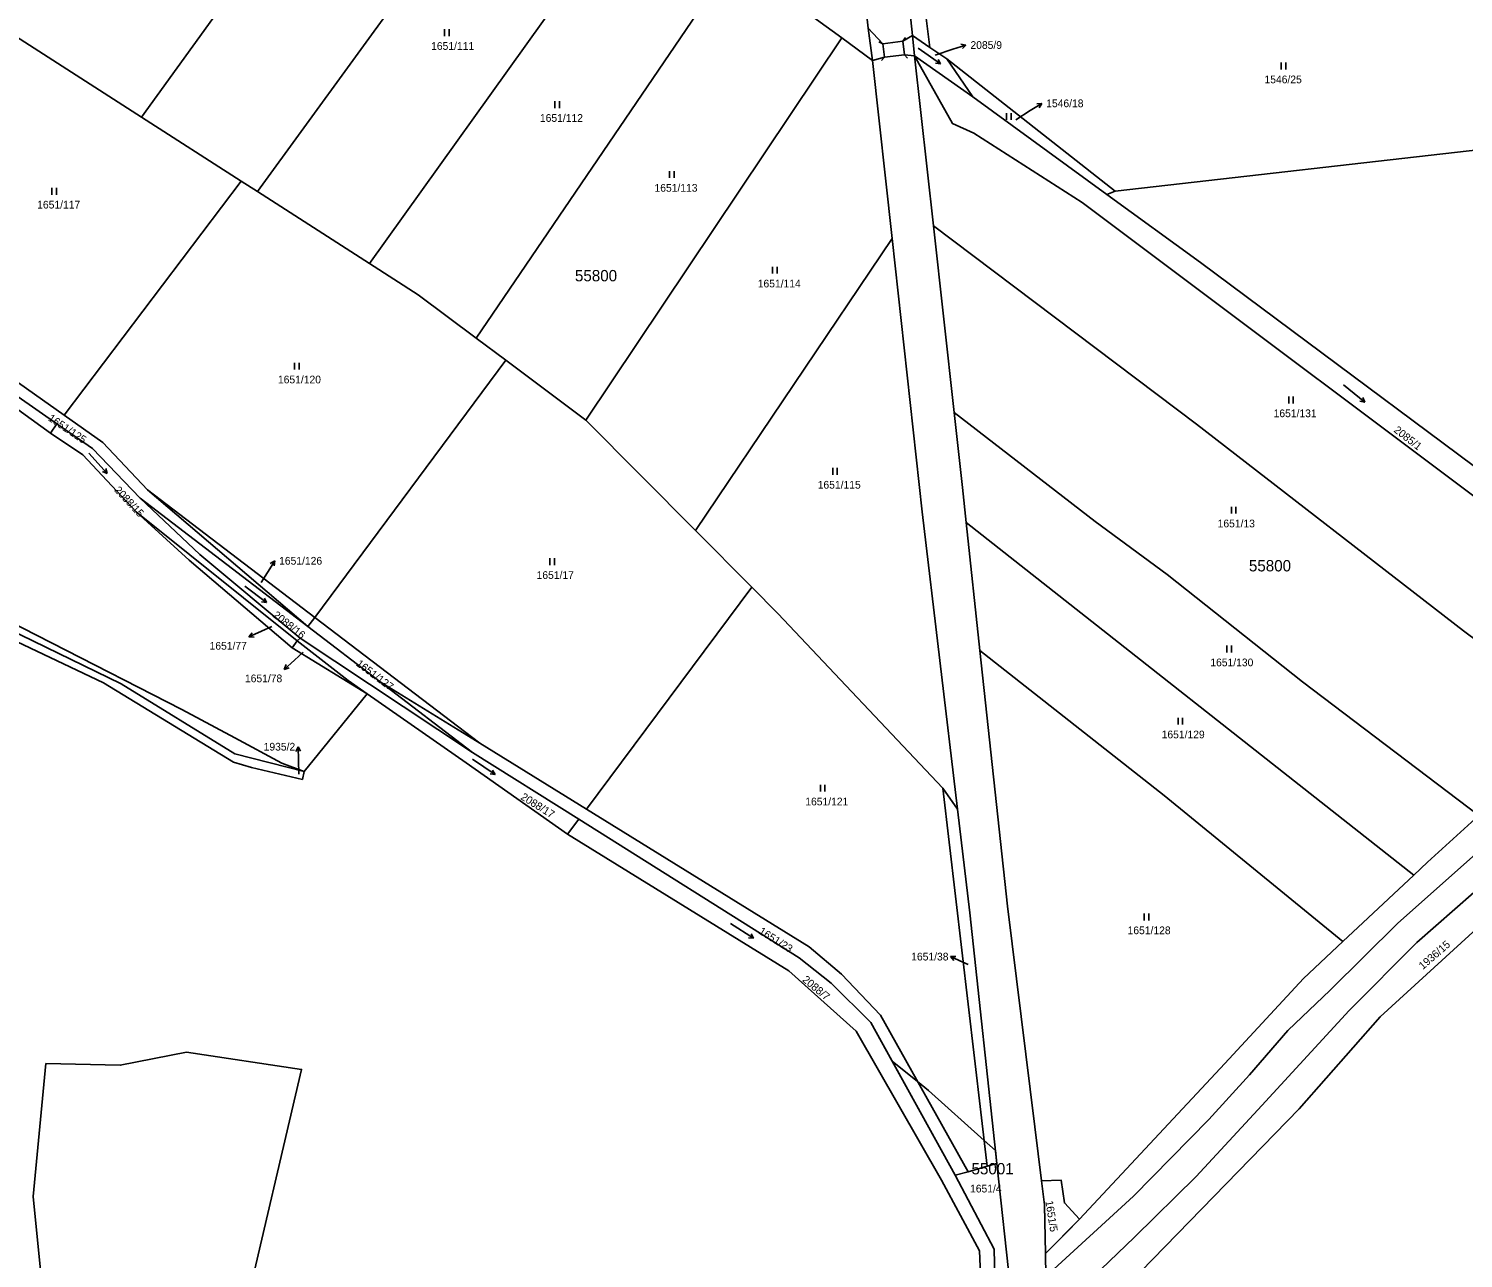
# Model space of a CAD drawing. Extents: x -794765 to -785424, y -1118958 to -1108731.
# Drawn here: x -792685.9 to -792369.7, y -1111701.3 to -1111430.3 of the extents above; entities that cross this region are included whole.
import ezdxf

# ---------------------------------------------------------------- set-up
doc = ezdxf.new("R2010")
doc.units = 0
for name, color, linetype in [('Level 66', 7, 'Continuous'), ('Level 75', 7, 'Continuous'), ('Level 76', 7, 'Continuous'), ('Level 77', 7, 'Continuous'), ('Level 80', 7, 'Continuous'), ('Level 81', 7, 'Continuous'), ('Vrstva 53', 7, 'Continuous')]:
    doc.layers.add(name, color=color, linetype=linetype)

msp = doc.modelspace()

# ---------------------------------------------------------------- linework, layer by layer
at = {"layer": 'Level 66'}
for p, q in [((-792594.27, -1111431.92), (-792594.27, -1111430.42)), ((-792593.27, -1111431.92), (-792593.27, -1111430.42)), ((-792489.85, -1111434.6), (-792484.93, -1111438.04)), ((-792484.93, -1111438.04), (-792486.02, -1111437.89)), ((-792484.93, -1111438.04), (-792485.45, -1111437.07)), ((-792409.84, -1111439.29), (-792409.84, -1111437.79)), ((-792408.84, -1111439.29), (-792408.84, -1111437.79)), ((-792569.92, -1111447.79), (-792569.92, -1111446.29)), ((-792568.92, -1111447.79), (-792568.92, -1111446.29)), ((-792470.35, -1111450.39), (-792470.35, -1111448.89)), ((-792469.35, -1111450.39), (-792469.35, -1111448.89)), ((-792544.65, -1111463.19), (-792544.65, -1111461.69)), ((-792543.65, -1111463.19), (-792543.65, -1111461.69)), ((-792680.84, -1111466.89), (-792680.84, -1111465.39)), ((-792679.84, -1111466.89), (-792679.84, -1111465.39)), ((-792521.97, -1111484.28), (-792521.97, -1111482.78)), ((-792520.97, -1111484.28), (-792520.97, -1111482.78)), ((-792627.34, -1111505.43), (-792627.34, -1111503.93)), ((-792626.34, -1111505.43), (-792626.34, -1111503.93)), ((-792396.07, -1111508.83), (-792391.41, -1111512.6)), ((-792408.17, -1111512.88), (-792408.17, -1111511.38)), ((-792407.17, -1111512.88), (-792407.17, -1111511.38)), ((-792391.41, -1111512.6), (-792392.49, -1111512.38)), ((-792391.41, -1111512.6), (-792391.85, -1111511.6)), ((-792672.67, -1111523.86), (-792668.66, -1111528.32)), ((-792668.66, -1111528.32), (-792669.68, -1111527.93)), ((-792668.66, -1111528.32), (-792668.94, -1111527.26)), ((-792508.7, -1111528.63), (-792508.7, -1111527.13)), ((-792507.7, -1111528.63), (-792507.7, -1111527.13)), ((-792420.81, -1111537.16), (-792420.81, -1111535.66)), ((-792419.81, -1111537.16), (-792419.81, -1111535.66)), ((-792571.05, -1111548.53), (-792571.05, -1111547.03)), ((-792570.05, -1111548.53), (-792570.05, -1111547.03)), ((-792638.3, -1111553.18), (-792633.51, -1111556.79)), ((-792633.51, -1111556.79), (-792634.59, -1111556.6)), ((-792633.51, -1111556.79), (-792633.98, -1111555.8)), ((-792421.79, -1111567.78), (-792421.79, -1111566.28)), ((-792420.79, -1111567.78), (-792420.79, -1111566.28)), ((-792432.55, -1111583.66), (-792432.55, -1111582.16)), ((-792431.55, -1111583.66), (-792431.55, -1111582.16)), ((-792588.11, -1111591.34), (-792583.13, -1111594.69)), ((-792583.13, -1111594.69), (-792584.22, -1111594.56)), ((-792583.13, -1111594.69), (-792583.66, -1111593.73)), ((-792511.42, -1111598.44), (-792511.42, -1111596.94)), ((-792510.42, -1111598.44), (-792510.42, -1111596.94)), ((-792531.19, -1111627.49), (-792526.15, -1111630.76)), ((-792440.04, -1111626.83), (-792440.04, -1111625.33)), ((-792439.04, -1111626.83), (-792439.04, -1111625.33)), ((-792526.15, -1111630.76), (-792527.25, -1111630.65)), ((-792526.15, -1111630.76), (-792526.7, -1111629.81))]:
    msp.add_line(p, q, dxfattribs=at)
at = {"layer": 'Level 75'}
for p, q in [((-792661.06, -1111449.81), (-792600.1, -1111365.36)), ((-792635.5, -1111466.22), (-792575.06, -1111383.02)), ((-792610.83, -1111482.05), (-792551.75, -1111399.53)), ((-792587.28, -1111498.52), (-792530.56, -1111414.97)), ((-792530.56, -1111414.97), (-792506.69, -1111432.36)), ((-792487.27, -1111434.43), (-792488.15, -1111427.37)), ((-792693.59, -1111428.94), (-792661.06, -1111449.81)), ((-792499.9, -1111437.31), (-792500.86, -1111430.2)), ((-792563.09, -1111516.61), (-792506.69, -1111432.36)), ((-792506.69, -1111432.36), (-792499.9, -1111437.31)), ((-792487.27, -1111434.43), (-792491.13, -1111431.81)), ((-792491.13, -1111431.81), (-792490.63, -1111436.28)), ((-792483.54, -1111436.96), (-792487.27, -1111434.43)), ((-792499.9, -1111437.31), (-792495.59, -1111476.54)), ((-792490.63, -1111436.28), (-792477.82, -1111445.31)), ((-792486.49, -1111473.79), (-792490.63, -1111436.28)), ((-792477.82, -1111445.31), (-792483.54, -1111436.96)), ((-792446.42, -1111466.11), (-792483.54, -1111436.96)), ((-792448.26, -1111466.82), (-792477.82, -1111445.31)), ((-792661.06, -1111449.81), (-792639.08, -1111463.92)), ((-792446.42, -1111466.11), (-792336.43, -1111453.6)), ((-792678.13, -1111515.48), (-792639.08, -1111463.92)), ((-792639.08, -1111463.92), (-792635.5, -1111466.22)), ((-792635.5, -1111466.22), (-792610.83, -1111482.05)), ((-792448.26, -1111466.82), (-792446.42, -1111466.11)), ((-792486.49, -1111473.79), (-792481.94, -1111514.93)), ((-792538.93, -1111540.93), (-792495.59, -1111476.54)), ((-792711.08, -1111495.6), (-792679.73, -1111517.41)), ((-792701.37, -1111499.06), (-792678.13, -1111515.48)), ((-792587.28, -1111498.52), (-792580.77, -1111503.39)), ((-792580.77, -1111503.39), (-792622.84, -1111560.08)), ((-792563.09, -1111516.61), (-792580.77, -1111503.39)), ((-792538.93, -1111540.93), (-792563.09, -1111516.61)), ((-792681.1, -1111519.43), (-792679.73, -1111517.41)), ((-792659.73, -1111531.96), (-792622.84, -1111560.08)), ((-792624.37, -1111562.09), (-792659.73, -1111531.96)), ((-792661.39, -1111533.79), (-792624.37, -1111562.09)), ((-792626.76, -1111565.23), (-792662.23, -1111536.79)), ((-792476.24, -1111567.39), (-792479.28, -1111539.17)), ((-792380.6, -1111616.86), (-792479.28, -1111539.17)), ((-792526.51, -1111553.43), (-792538.93, -1111540.93)), ((-792562.99, -1111602.32), (-792526.51, -1111553.43)), ((-792710.23, -1111555.16), (-792669.41, -1111574.48)), ((-792624.37, -1111562.09), (-792622.84, -1111560.08)), ((-792622.84, -1111560.08), (-792586.5, -1111587.78)), ((-792624.37, -1111562.09), (-792608.44, -1111574.27)), ((-792627.85, -1111566.78), (-792626.76, -1111565.23)), ((-792611.35, -1111576.91), (-792627.85, -1111566.78)), ((-792626.76, -1111565.23), (-792626.11, -1111564.6)), ((-792626.11, -1111564.6), (-792588.08, -1111589.84)), ((-792669.41, -1111574.48), (-792640.78, -1111591.95)), ((-792625.2, -1111594.04), (-792611.35, -1111576.91)), ((-792586.5, -1111587.78), (-792608.44, -1111574.27)), ((-792608.44, -1111574.27), (-792588.08, -1111589.84)), ((-792588.08, -1111589.84), (-792564.67, -1111604.56)), ((-792586.5, -1111587.78), (-792562.99, -1111602.32)), ((-792640.78, -1111591.95), (-792636.82, -1111593.12)), ((-792484.4, -1111597.73), (-792474.62, -1111681.02)), ((-792481.17, -1111602.31), (-792484.4, -1111597.73)), ((-792564.67, -1111604.56), (-792567.14, -1111607.86)), ((-792380.6, -1111616.86), (-792396.21, -1111631.51)), ((-792474.62, -1111681.02), (-792478.83, -1111682.26)), ((-792472.48, -1111680.42), (-792474.62, -1111681.02)), ((-792472.48, -1111680.42), (-792469.49, -1111708.06)), ((-792478.83, -1111682.26), (-792481.68, -1111682.99)), ((-792454.29, -1111692.72), (-792461.78, -1111700.29))]:
    msp.add_line(p, q, dxfattribs=at)
for points in [[(-792491.13, -1111431.81), (-792491.51, -1111428.33), (-792497.74, -1111372.23)], [(-792490.63, -1111436.28), (-792482.27, -1111451.23), (-792477.59, -1111453.34), (-792453.68, -1111468.58), (-792349.47, -1111546.81)], [(-792339.24, -1111548.69), (-792343.91, -1111544.15), (-792427.64, -1111481.83), (-792448.26, -1111466.82)], [(-792343.17, -1111582.69), (-792369.63, -1111563.05), (-792428.51, -1111517.47), (-792486.49, -1111473.79)], [(-792495.59, -1111476.54), (-792488.97, -1111536.76), (-792481.17, -1111602.31)], [(-792610.83, -1111482.05), (-792600.05, -1111488.97), (-792587.28, -1111498.52)], [(-792681.1, -1111519.43), (-792711.34, -1111497.65), (-792713.25, -1111495.39)], [(-792678.13, -1111515.48), (-792669.61, -1111521.5), (-792659.73, -1111531.96)], [(-792479.28, -1111539.17), (-792480.12, -1111531.4), (-792481.94, -1111514.93)], [(-792481.94, -1111514.93), (-792450.85, -1111538.95), (-792434.95, -1111550.6), (-792405.11, -1111574.24), (-792366.26, -1111603.72)], [(-792662.23, -1111536.79), (-792674.02, -1111524.21), (-792681.1, -1111519.43)], [(-792679.73, -1111517.41), (-792671.89, -1111522.86), (-792661.39, -1111533.79)], [(-792626.11, -1111564.6), (-792648.22, -1111546.21), (-792661.39, -1111533.79)], [(-792627.85, -1111566.78), (-792650.58, -1111547.47), (-792662.23, -1111536.79)], [(-792709.69, -1111550.99), (-792652.17, -1111580.36), (-792640.47, -1111586.61), (-792630.1, -1111592.15), (-792625.2, -1111594.04)], [(-792709.89, -1111553.21), (-792665.52, -1111574.73), (-792640.49, -1111590.16), (-792625.2, -1111594.04)], [(-792526.51, -1111553.43), (-792520.8, -1111559.18), (-792484.4, -1111597.73)], [(-792611.35, -1111576.91), (-792615.54, -1111574), (-792626.76, -1111565.23)], [(-792462.65, -1111684.23), (-792464.15, -1111672.32), (-792470.18, -1111623.67), (-792476.24, -1111567.39)], [(-792396.21, -1111631.51), (-792435.63, -1111599.33), (-792476.24, -1111567.39)], [(-792611.35, -1111576.91), (-792589.53, -1111592.09), (-792567.14, -1111607.86)], [(-792461.51, -1111714.48), (-792449.61, -1111703.78), (-792442.2, -1111696.63), (-792428.56, -1111683.25), (-792414.13, -1111667.62), (-792394.83, -1111646.68), (-792379.95, -1111631.73), (-792358.99, -1111613.36), (-792335.63, -1111592.95), (-792316, -1111574.96), (-792315.09, -1111574.03)], [(-792461.41, -1111719.58), (-792443.5, -1111707.04), (-792405.88, -1111668.37), (-792387.98, -1111648.11), (-792359.94, -1111622.42), (-792311.35, -1111577.41)], [(-792636.82, -1111593.12), (-792625.6, -1111595.75), (-792625.2, -1111594.04)], [(-792478.83, -1111682.26), (-792498.18, -1111647.73), (-792506.75, -1111638.68), (-792513.86, -1111632.7), (-792562.99, -1111602.32)], [(-792472.48, -1111680.42), (-792478.45, -1111625.15), (-792481.17, -1111602.31)], [(-792564.67, -1111604.56), (-792516.09, -1111635.11), (-792509.06, -1111640.65), (-792500.3, -1111649.32), (-792481.68, -1111682.99)], [(-792366.26, -1111603.72), (-792377.58, -1111614.03), (-792380.6, -1111616.86)], [(-792567.14, -1111607.86), (-792518.38, -1111637.95), (-792503.52, -1111651.22), (-792484.69, -1111684.09), (-792476.33, -1111699.64), (-792475.74, -1111713.71)], [(-792396.21, -1111631.51), (-792404.9, -1111639.66), (-792422.23, -1111658.36), (-792454.29, -1111692.72)], [(-792651.15, -1111655.88), (-792665.74, -1111658.77), (-792682.13, -1111658.41), (-792684.95, -1111687.66), (-792682.27, -1111714.24), (-792680.86, -1111742.68), (-792684.79, -1111773.8)], [(-792638.49, -1111714.03), (-792625.78, -1111659.69), (-792651.15, -1111655.88)], [(-792481.68, -1111682.99), (-792473.08, -1111699.31), (-792472.84, -1111711.97)], [(-792462.65, -1111684.23), (-792458.31, -1111684.1), (-792457.6, -1111689.12), (-792454.29, -1111692.72)], [(-792461.78, -1111700.29), (-792461.99, -1111689.5), (-792462.65, -1111684.23)], [(-792461.78, -1111700.29), (-792461.68, -1111705.3), (-792461.51, -1111714.48)]]:
    msp.add_lwpolyline(points, dxfattribs=at)
at = {"layer": 'Level 77'}
for p, q in [((-792500.86, -1111430.2), (-792497.65, -1111433.63)), ((-792498.55, -1111433.19), (-792497.65, -1111433.63)), ((-792497.65, -1111433.63), (-792493.26, -1111433.03)), ((-792497.65, -1111433.63), (-792497.3, -1111436.57)), ((-792493.26, -1111433.03), (-792491.13, -1111431.81)), ((-792492.62, -1111432.26), (-792493.26, -1111433.03)), ((-792493.26, -1111433.03), (-792492.9, -1111436.04)), ((-792499.9, -1111437.31), (-792497.3, -1111436.57)), ((-792497.93, -1111437.35), (-792497.3, -1111436.57)), ((-792497.3, -1111436.57), (-792492.9, -1111436.04)), ((-792492.23, -1111436.78), (-792492.9, -1111436.04)), ((-792492.9, -1111436.04), (-792490.63, -1111436.28)), ((-792384.11, -1111627.47), (-792363.02, -1111608.73)), ((-792399.06, -1111642.23), (-792384.11, -1111627.47)), ((-792399.06, -1111642.23), (-792408.36, -1111651.07)), ((-792408.36, -1111651.07), (-792416.83, -1111660.88)), ((-792416.83, -1111660.88), (-792425.75, -1111670.7)), ((-792425.75, -1111670.7), (-792442.4, -1111687.65)), ((-792442.4, -1111687.65), (-792461.68, -1111705.3))]:
    msp.add_line(p, q, dxfattribs=at)
at = {"layer": 'Level 80'}
for p, q in [((-792486.08, -1111436.12), (-792482.18, -1111434.84)), ((-792482.18, -1111434.84), (-792479.33, -1111433.91)), ((-792479.33, -1111433.91), (-792480.43, -1111433.75)), ((-792479.33, -1111433.91), (-792480.12, -1111434.7)), ((-792465.16, -1111448.37), (-792462.61, -1111446.78)), ((-792462.61, -1111446.78), (-792463.73, -1111446.89)), ((-792462.61, -1111446.78), (-792463.2, -1111447.74)), ((-792468.34, -1111450.39), (-792465.16, -1111448.37)), ((-792633.3, -1111550.14), (-792631.71, -1111547.59)), ((-792631.71, -1111547.59), (-792632.67, -1111548.18)), ((-792631.71, -1111547.59), (-792631.82, -1111548.71)), ((-792634.66, -1111552.36), (-792633.3, -1111550.14)), ((-792634.64, -1111563.12), (-792637.38, -1111564.34)), ((-792637.38, -1111564.34), (-792636.67, -1111563.48)), ((-792637.38, -1111564.34), (-792636.26, -1111564.39)), ((-792632.36, -1111562.1), (-792634.64, -1111563.12)), ((-792627.36, -1111569.5), (-792629.59, -1111571.51)), ((-792629.59, -1111571.51), (-792629.18, -1111570.47)), ((-792625.42, -1111567.74), (-792627.36, -1111569.5)), ((-792629.59, -1111571.51), (-792628.51, -1111571.21)), ((-792626.56, -1111588.56), (-792627.02, -1111589.58)), ((-792626.45, -1111591.56), (-792626.56, -1111588.56)), ((-792626.56, -1111588.56), (-792626.02, -1111589.54)), ((-792626.37, -1111594.58), (-792626.45, -1111591.56)), ((-792482.7, -1111634.8), (-792481.58, -1111634.77)), ((-792479.98, -1111636.07), (-792482.7, -1111634.8)), ((-792482.7, -1111634.8), (-792482, -1111635.68)), ((-792478.86, -1111636.59), (-792479.98, -1111636.07))]:
    msp.add_line(p, q, dxfattribs=at)
at = {"layer": 'Level 81'}
for points in [[(-792491.51, -1111428.33), (-792491.13, -1111431.81), (-792487.27, -1111434.43), (-792483.54, -1111436.96), (-792477.82, -1111445.31), (-792448.26, -1111466.82), (-792427.64, -1111481.83), (-792343.91, -1111544.15)], [(-792349.47, -1111546.81), (-792453.68, -1111468.58), (-792477.59, -1111453.34), (-792482.27, -1111451.23), (-792490.63, -1111436.28), (-792486.49, -1111473.79), (-792481.94, -1111514.93), (-792480.12, -1111531.4), (-792479.28, -1111539.17), (-792476.24, -1111567.39), (-792470.18, -1111623.67), (-792464.15, -1111672.32), (-792462.65, -1111684.23), (-792461.99, -1111689.5), (-792461.99, -1111689.62), (-792461.78, -1111700.29), (-792457.39, -1111695.85), (-792454.29, -1111692.72), (-792422.23, -1111658.36), (-792404.9, -1111639.66), (-792396.21, -1111631.51), (-792380.6, -1111616.86), (-792377.58, -1111614.03), (-792366.26, -1111603.72)], [(-792495.59, -1111657.83), (-792500.3, -1111649.32), (-792509.06, -1111640.65), (-792516.09, -1111635.11), (-792564.67, -1111604.56), (-792588.08, -1111589.84), (-792608.44, -1111574.27), (-792624.37, -1111562.09)], [(-792495.59, -1111657.83), (-792489.97, -1111662.37), (-792487.57, -1111664.32), (-792475.29, -1111675.34), (-792472.79, -1111677.58)], [(-792495.59, -1111657.83), (-792481.68, -1111682.99), (-792473.08, -1111699.31), (-792472.84, -1111711.97)], [(-792472.79, -1111677.58), (-792472.48, -1111680.42), (-792469.49, -1111708.06)]]:
    msp.add_lwpolyline(points, dxfattribs=at)
at = {"layer": 'Vrstva 53'}
for points in [[(-792481.17, -1111602.31), (-792488.97, -1111536.76), (-792495.59, -1111476.54), (-792499.9, -1111437.31), (-792500.86, -1111430.2), (-792508.08, -1111366.67), (-792513.59, -1111316.17), (-792518.85, -1111267.98), (-792528.81, -1111180.11), (-792532.58, -1111147.1), (-792532.87, -1111142.24), (-792534.46, -1111129.2), (-792535.27, -1111122.6), (-792537.05, -1111104.14), (-792537.86, -1111098.92), (-792549, -1111003.82), (-792549.58, -1110998.89), (-792549.9, -1110996.2), (-792550.9, -1110987.8), (-792552.78, -1110972.03), (-792564.11, -1110874.31), (-792564.67, -1110869.51), (-792573.72, -1110796.5), (-792583.08, -1110701.05)], [(-792524.99, -1111145.74), (-792505.91, -1111301.51), (-792502.48, -1111329.5), (-792497.74, -1111372.23), (-792491.51, -1111428.33), (-792491.13, -1111431.81), (-792490.63, -1111436.28), (-792486.49, -1111473.79), (-792481.94, -1111514.93), (-792480.12, -1111531.4), (-792479.28, -1111539.17), (-792476.24, -1111567.39), (-792470.18, -1111623.67)]]:
    msp.add_lwpolyline(points, dxfattribs=at)

# ---------------------------------------------------------------- texts
at = {"layer": 'Level 76'}
for s, p in [('1651/111', (-792597.22, -1111434.97)), ('2085/9', (-792478.33, -1111434.76)), ('1546/25', (-792413.51, -1111442.34)), ('1546/18', (-792461.63, -1111447.61)), ('1651/112', (-792573.24, -1111450.84)), ('1651/113', (-792547.98, -1111466.24)), ('1651/117', (-792684.06, -1111469.94)), ('1651/114', (-792525.22, -1111487.33)), ('1651/120', (-792630.99, -1111508.48)), ('1651/131', (-792411.5, -1111515.93)), ('1651/115', (-792512, -1111531.68)), ('1651/13', (-792423.84, -1111540.21)), ('1651/126', (-792630.73, -1111548.43)), ('1651/17', (-792573.97, -1111551.58)), ('1651/77', (-792646.06, -1111567.17)), ('1651/130', (-792425.45, -1111570.83)), ('1651/78', (-792638.26, -1111574.35)), ('1651/129', (-792436.18, -1111586.71)), ('1935/2', (-792634.14, -1111589.41)), ('1651/121', (-792514.74, -1111601.49)), ('1651/128', (-792443.69, -1111629.88)), ('1651/38', (-792491.39, -1111635.67)), ('1651/4', (-792478.42, -1111686.8))]:
    msp.add_text(s, height=1.7, dxfattribs=at).set_placement(p)
for s, rotation, p in [('1651/125', 326, (-792681.81, -1111516.53)), ('2085/1', 322, (-792385.15, -1111519.05)), ('2088/15', 313, (-792667.19, -1111532.1)), ('2088/16', 322, (-792632.26, -1111559.84)), ('1651/127', 323, (-792613.9, -1111570.57)), ('2088/17', 328, (-792577.64, -1111600.04)), ('1651/23', 328, (-792525.16, -1111629.66)), ('1936/15', 41, (-792378.6, -1111637.78)), ('2088/7', 320, (-792515.53, -1111640.14)), ('1651/5', 279, (-792461.82, -1111688.72))]:
    msp.add_text(s, height=1.7, rotation=rotation, dxfattribs=at).set_placement(p)
at = {"layer": 'Level 81'}
for s, p in [('55800', (-792565.52, -1111485.99)), ('55800', (-792416.95, -1111549.92)), ('55001', (-792478.1, -1111682.81))]:
    msp.add_text(s, height=2.5, dxfattribs=at).set_placement(p)

doc.saveas('drawing.dxf')
